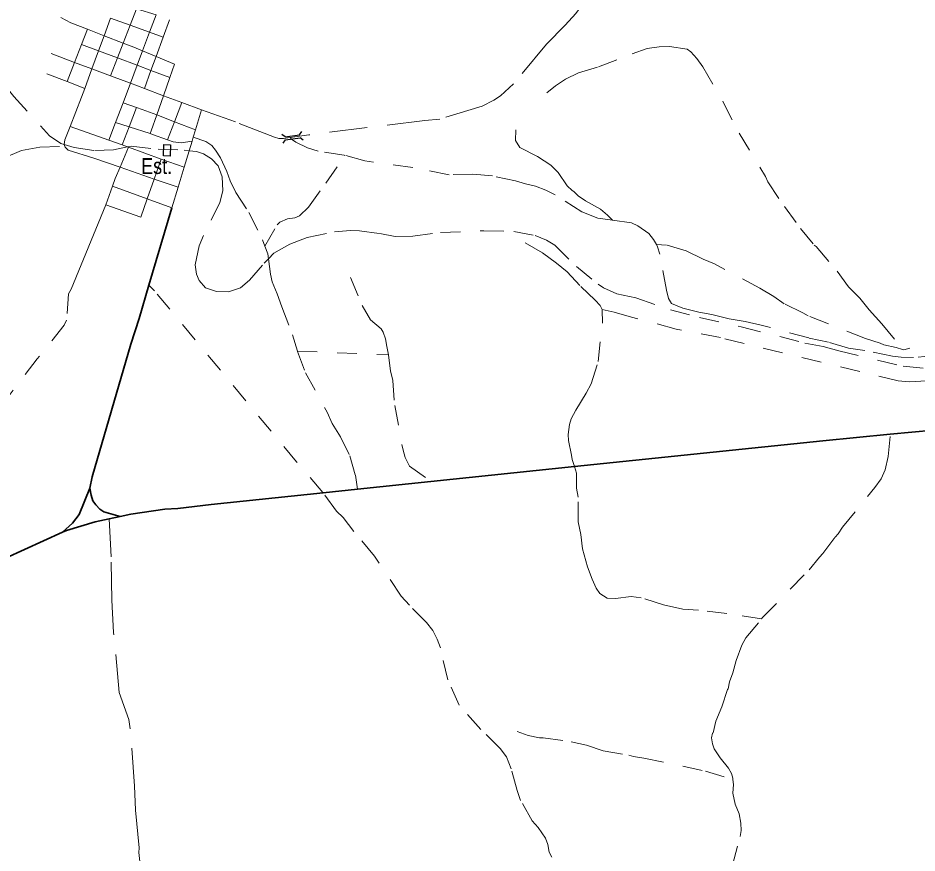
# Model space of a CAD drawing. Extents: x 783.4 to 809.8, y 7536.4 to 7564.6.
# Drawn here: x 790.875 to 795.406, y 7553.23 to 7557.441 of the extents above; entities that cross this region are included whole.
import ezdxf
from ezdxf.enums import TextEntityAlignment as Align

# ---------------------------------------------------------------- set-up
doc = ezdxf.new("R2010")
doc.units = 0
doc.header["$LTSCALE"] = 0.032
for name, pattern in [('DOTTED', [1.5, 0.3, -1.2]), ('LONG_DASHED', [7.5, 6, -1.5]), ('MEDIUM_DASHED', [4.5, 3, -1.5])]:
    doc.linetypes.add(name, pattern=pattern)
for name, color, linetype, lineweight in [('10', 7, 'Continuous', 25), ('18', 7, 'DOTTED', 13), ('2', 7, 'Continuous', 35), ('28', 7, 'Continuous', 25), ('5', 7, 'LONG_DASHED', 13), ('6', 7, 'MEDIUM_DASHED', 13), ('7', 7, 'DOTTED', 13), ('8', 7, 'Continuous', 13)]:
    doc.layers.add(name, color=color, linetype=linetype, lineweight=lineweight)
doc.layers.add('61', color=7, linetype='Continuous')

msp = doc.modelspace()

# ---------------------------------------------------------------- linework, layer by layer
at = {"layer": '10'}
for p, q in [((792.2208, 7556.8422), (792.205, 7556.8543)), ((792.2111, 7556.8105), (792.223, 7556.8264)), ((792.223, 7556.8264), (792.2963, 7556.8367)), ((792.3123, 7556.8247), (792.2963, 7556.8367))]:
    msp.add_line(p, q, dxfattribs=at)
msp.add_lwpolyline([(792.2208, 7556.8422), (792.2941, 7556.8525), (792.3061, 7556.8685)], dxfattribs=at)
at = {"layer": '18'}
for points in [[(790.5277, 7557.551), (790.6798, 7557.3347), (790.764, 7557.1684), (790.8086, 7557.1021), (790.8537, 7557.0458), (791.0331, 7556.8465), (791.0907, 7556.8075), (791.1076, 7556.8025)], [(791.1076, 7556.8025), (791.1579, 7556.7878), (791.2621, 7556.7727), (791.3563, 7556.7765), (791.4272, 7556.7908)], [(791.4272, 7556.7908), (791.4445, 7556.7943), (791.5807, 7556.7789), (791.712, 7556.7751), (791.7377, 7556.7721)], [(791.7377, 7556.7721), (791.7752, 7556.7676), (791.8102, 7556.7563), (791.8493, 7556.7309), (791.8834, 7556.6962), (791.9034, 7556.6407), (791.9065, 7556.5693), (791.8924, 7556.511), (791.8098, 7556.3451), (791.7887, 7556.2925), (791.7677, 7556.1957), (791.7747, 7556.1497), (791.7872, 7556.1182), (791.8203, 7556.0806), (791.8744, 7556.0618), (791.9365, 7556.06), (791.9957, 7556.0797), (792.0418, 7556.1192), (792.1149, 7556.2056), (792.1371, 7556.2273)], [(792.1371, 7556.2273), (792.165, 7556.2545), (792.2457, 7556.301), (792.3319, 7556.3349), (792.4702, 7556.3631), (792.5514, 7556.3696), (792.5965, 7556.3687), (792.6982, 7556.3541), (792.7754, 7556.3391), (792.8656, 7556.341), (793.0049, 7556.3588), (793.2229, 7556.3687), (793.3732, 7556.364), (793.4819, 7556.3447), (793.5391, 7556.3212), (793.5801, 7556.2958), (793.6905, 7556.1877), (793.7982, 7556.0989), (793.8263, 7556.0801), (793.8934, 7556.05), (793.9896, 7556.0294), (794.1635, 7555.9697), (794.3098, 7555.9302), (794.5203, 7555.8842), (794.8405, 7555.802), (794.9337, 7555.7851), (795.0124, 7555.7621), (795.3371, 7555.685), (795.4657, 7555.6734)]]:
    msp.add_lwpolyline(points, dxfattribs=at)
at = {"layer": '2'}
for p, q in [((791.6509, 7556.4844), (791.5349, 7556.0935)), ((792.9563, 7555.1033), (793.6797, 7555.1787)), ((791.3337, 7554.9157), (791.389, 7554.9276))]:
    msp.add_line(p, q, dxfattribs=at)
for points in [[(791.5349, 7556.0935), (791.4854, 7555.9265), (791.4441, 7555.7966), (791.2483, 7555.1272), (791.2375, 7555.0707), (791.2373, 7555.0702)], [(793.6797, 7555.1787), (794.9319, 7555.3091), (795.2716, 7555.3423), (795.4886, 7555.3627)], [(792.4125, 7555.0467), (792.5856, 7555.0647), (792.9563, 7555.1033)], [(791.2373, 7555.0702), (791.1834, 7554.9382), (791.1498, 7554.8937), (791.0992, 7554.8479)], [(791.2373, 7555.0702), (791.2433, 7555.0356), (791.2525, 7555.0067), (791.2672, 7554.9857), (791.288, 7554.9647), (791.3074, 7554.9509), (791.389, 7554.9276)], [(791.389, 7554.9276), (791.4441, 7554.9395), (791.6155, 7554.9639), (791.6796, 7554.9677), (791.8485, 7554.9879), (792.4125, 7555.0467)], [(791.0992, 7554.8479), (791.1199, 7554.8573), (791.2632, 7554.9005), (791.3337, 7554.9157)], [(788.9236, 7554.2237), (789.0729, 7554.2243), (789.2498, 7554.221), (789.4603, 7554.2361), (789.6116, 7554.2549), (789.8015, 7554.2901), (789.9318, 7554.324), (790.021, 7554.3531), (790.274, 7554.4729), (790.3763, 7554.5133), (790.5902, 7554.6163), (790.6187, 7554.6293), (791.0992, 7554.8479)]]:
    msp.add_lwpolyline(points, dxfattribs=at)
at = {"layer": '28'}
msp.add_lwpolyline([(791.6083, 7556.7454), (791.6103, 7556.8024), (791.6442, 7556.8012), (791.6422, 7556.7442)], close=True, dxfattribs=at)
at = {"layer": '5'}
for points in [[(793.7415, 7559.6693), (793.6938, 7559.5981), (793.6538, 7559.5517), (793.6122, 7559.5165), (793.5506, 7559.4757), (793.3394, 7559.3621), (793.2354, 7559.2901), (793.1594, 7559.2301), (792.8826, 7558.9893), (792.6978, 7558.8372), (792.5706, 7558.7236), (792.3033, 7558.5012), (792.2673, 7558.4596), (792.0593, 7558.1564), (791.7425, 7557.7044), (791.6062, 7557.3449)], [(793.9831, 7557.8046), (793.8466, 7557.6892), (793.7962, 7557.6276), (793.7498, 7557.5508), (793.6866, 7557.4644), (793.633, 7557.4044), (793.5386, 7557.3084), (793.3722, 7557.1084), (793.3066, 7557.0484), (793.2738, 7557.026), (793.2148, 7556.9963), (793.0003, 7556.9315), (792.9252, 7556.9249), (792.34, 7556.8516), (792.2471, 7556.8378)], [(791.0906, 7557.4429), (791.1407, 7557.4175), (791.2243, 7557.3844)], [(792.2471, 7556.8378), (792.2137, 7556.8328), (792.1897, 7556.8337), (792.1676, 7556.8394), (791.9707, 7556.9169), (791.7997, 7556.9776)], [(791.8674, 7552.2937), (791.8681, 7552.301), (791.8665, 7552.349), (791.8593, 7552.397), (791.8465, 7552.445), (791.8249, 7552.493), (791.7761, 7552.565), (791.6377, 7552.7362), (791.5801, 7552.8154), (791.5377, 7552.8962), (791.5241, 7552.9442), (791.5001, 7553.0882), (791.4841, 7553.2322), (791.4849, 7553.2562), (791.4665, 7553.4482), (791.4617, 7553.5683), (791.4409, 7553.8563), (791.4329, 7553.9043), (791.3848, 7554.0396), (791.3569, 7554.3427), (791.3481, 7554.5059), (791.3441, 7554.7235), (791.3337, 7554.9157)]]:
    msp.add_lwpolyline(points, dxfattribs=at)
at = {"layer": '6'}
for points in [[(791.7581, 7556.8397), (791.8213, 7556.8178), (791.8511, 7556.7985), (791.871, 7556.7752), (791.8952, 7556.7365), (791.9271, 7556.6666), (791.9435, 7556.6206), (791.9719, 7556.5613), (792.039, 7556.4604), (792.1072, 7556.3232), (792.1192, 7556.2913)], [(790.8012, 7556.7351), (790.8928, 7556.7731), (790.9844, 7556.7903), (791.1109, 7556.793)], [(792.1192, 7556.2913), (792.1338, 7556.2523), (792.1371, 7556.2273)], [(792.1371, 7556.2273), (792.1473, 7556.1497), (792.1559, 7556.1104), (792.1818, 7556.0507), (792.2038, 7555.9848), (792.2585, 7555.8436), (792.2829, 7555.7615)], [(792.4125, 7555.0467), (792.4116, 7555.0478), (792.2792, 7555.2032), (791.562, 7556.0658), (791.5349, 7556.0935)], [(791.1424, 7556.073), (791.1296, 7556.051), (791.12, 7555.9173), (791.108, 7555.892), (790.9719, 7555.7223), (790.7713, 7555.4611)], [(792.2829, 7555.7615), (792.2837, 7555.7587), (792.3242, 7555.6521), (792.4326, 7555.454), (792.4585, 7555.3971), (792.5002, 7555.3299), (792.5474, 7555.2339), (792.5751, 7555.1357), (792.5856, 7555.0647)], [(793.5653, 7553.2099), (793.552, 7553.2341), (793.5446, 7553.2737), (793.5335, 7553.3056), (793.4958, 7553.3583), (793.4658, 7553.3926), (793.4081, 7553.4953), (793.3904, 7553.546), (793.3611, 7553.6552), (793.3374, 7553.7162), (793.3056, 7553.7579), (793.2072, 7553.8536), (793.0988, 7553.9761), (793.0411, 7554.1044), (793.0037, 7554.2657), (792.9875, 7554.3087), (792.9653, 7554.3524), (792.9339, 7554.3923), (792.8473, 7554.4797), (792.8066, 7554.5262), (792.6716, 7554.7277), (792.5673, 7554.8519), (792.5144, 7554.9216), (792.4804, 7554.9542), (792.4125, 7555.0467)]]:
    msp.add_lwpolyline(points, dxfattribs=at)
at = {"layer": '7'}
msp.add_line((792.2829, 7555.7615), (792.7415, 7555.7425), dxfattribs=at)
for points in [[(793.5401, 7557.0641), (793.5833, 7557.0995), (793.634, 7557.1329), (793.6999, 7557.1643), (793.8002, 7557.1946), (793.9706, 7557.2612), (794.0466, 7557.2868), (794.1066, 7557.2964), (794.1594, 7557.298), (794.2474, 7557.2844), (794.2658, 7557.2708), (794.297, 7557.2372), (794.3266, 7557.1948), (794.4298, 7557.0164), (794.509, 7556.8604), (794.6426, 7556.6412), (794.6546, 7556.6148), (794.7378, 7556.49), (794.8194, 7556.3804), (794.8874, 7556.2964), (794.8978, 7556.2892), (795.0035, 7556.164), (795.0605, 7556.0856), (795.1174, 7556.028), (795.1644, 7555.9701), (795.2295, 7555.8994), (795.3334, 7555.7694)], [(793.3841, 7556.8765), (793.3818, 7556.8236), (793.405, 7556.7876), (793.4938, 7556.7428), (793.5602, 7556.6988), (793.597, 7556.6628), (793.6434, 7556.5956), (793.6674, 7556.5716), (793.677, 7556.566), (793.6978, 7556.5452), (793.7346, 7556.5196), (793.8106, 7556.4764), (793.8466, 7556.4476), (793.8719, 7556.4216)], [(792.5228, 7556.748), (792.5183, 7556.7492), (792.3885, 7556.7697), (792.3345, 7556.7863), (792.2746, 7556.8148), (792.2538, 7556.8293), (792.2471, 7556.8378)], [(792.1192, 7556.2913), (792.1808, 7556.398), (792.195, 7556.4123), (792.2332, 7556.4287), (792.2703, 7556.4328), (792.2933, 7556.444), (792.3391, 7556.488), (792.4264, 7556.6078), (792.5228, 7556.748)], [(793.8719, 7556.4216), (793.797, 7556.432), (793.7175, 7556.4629), (793.5828, 7556.5489), (793.5355, 7556.5725), (793.4829, 7556.5933), (793.4322, 7556.6047), (793.3827, 7556.62), (793.2658, 7556.645), (793.1674, 7556.6533), (793.0476, 7556.6511), (792.8649, 7556.6864), (792.6233, 7556.7208), (792.5228, 7556.748)], [(794.0924, 7556.2992), (794.0781, 7556.3245), (794.0544, 7556.3536), (793.999, 7556.3939), (793.9671, 7556.4084), (793.8719, 7556.4216)], [(793.8195, 7555.972), (793.8086, 7555.9908), (793.7845, 7556.0183), (793.7065, 7556.0923), (793.6427, 7556.1603), (793.5891, 7556.2051), (793.5181, 7556.2567), (793.4246, 7556.3105)], [(795.5113, 7555.7409), (795.3882, 7555.7289), (795.3264, 7555.7306), (795.2828, 7555.7355), (795.1429, 7555.7646), (795.0602, 7555.7755), (794.9594, 7555.8059), (794.8601, 7555.8278), (794.6203, 7555.893), (794.5393, 7555.9107), (794.4586, 7555.9239), (794.3721, 7555.9454), (794.307, 7555.9572), (794.226, 7555.9784), (794.169, 7556.0006), (794.1539, 7556.0272), (794.1436, 7556.0688), (794.1103, 7556.2506), (794.0988, 7556.2877), (794.0924, 7556.2992)], [(795.3334, 7555.7694), (795.3011, 7555.7795), (795.2395, 7555.7923), (795.2211, 7555.8011), (795.1458, 7555.8251), (794.8578, 7555.9387), (794.8314, 7555.9547), (794.7372, 7555.9997), (794.685, 7556.0367), (794.6137, 7556.0785), (794.3858, 7556.2014), (794.3285, 7556.2253), (794.2432, 7556.2671), (794.1439, 7556.2957), (794.0924, 7556.2992)], [(792.5512, 7556.1323), (792.6087, 7555.9921), (792.6512, 7555.9183), (792.7045, 7555.8741), (792.7153, 7555.8575), (792.7264, 7555.8229), (792.7339, 7555.7841), (792.7415, 7555.7425)], [(793.6797, 7555.1787), (793.6682, 7555.2145), (793.665, 7555.2371), (793.649, 7555.3107), (793.6474, 7555.3403), (793.6546, 7555.3907), (793.6634, 7555.4203), (793.6858, 7555.4643), (793.7386, 7555.5491), (793.7642, 7555.5971), (793.7986, 7555.7091), (793.8202, 7555.9027), (793.8195, 7555.972)], [(795.5115, 7555.6254), (795.4536, 7555.6118), (795.3681, 7555.6064), (795.3116, 7555.6118), (794.4159, 7555.8292), (794.1927, 7555.8727), (793.9673, 7555.9333), (793.88, 7555.958), (793.8195, 7555.972)], [(795.5643, 7555.8251), (795.3395, 7555.7675), (795.3334, 7555.7694)], [(792.7415, 7555.7425), (792.7443, 7555.727), (792.753, 7555.6627), (792.7634, 7555.6139), (792.7738, 7555.4867), (792.8154, 7555.2611), (792.8258, 7555.2243), (792.8474, 7555.1819), (792.9563, 7555.1033)], [(794.6229, 7554.4115), (794.628, 7554.4177), (794.8626, 7554.6587), (794.9138, 7554.7227), (794.9322, 7554.7411), (794.993, 7554.8235), (795.0082, 7554.8395), (795.0306, 7554.8739), (795.1939, 7555.0731), (795.2251, 7555.1179), (795.2451, 7555.1627), (795.2603, 7555.2307), (795.2716, 7555.3423)], [(794.6229, 7554.4115), (794.4482, 7554.4387), (794.305, 7554.4547), (794.2266, 7554.4603), (794.129, 7554.4811), (794.0162, 7554.5171), (793.9655, 7554.5237), (793.8858, 7554.5139), (793.8442, 7554.5163), (793.8066, 7554.5395), (793.7882, 7554.5667), (793.7682, 7554.6107), (793.745, 7554.6739), (793.7194, 7554.7651), (793.7114, 7554.8371), (793.6986, 7554.9011), (793.6986, 7555.0251), (793.6906, 7555.0707), (793.6898, 7555.1459), (793.6797, 7555.1787)], [(794.4785, 7553.6013), (794.4778, 7553.6071), (794.4711, 7553.6321), (794.4556, 7553.6578), (794.4146, 7553.7099), (794.3834, 7553.7555), (794.3746, 7553.7803), (794.3706, 7553.8115), (794.3754, 7553.8347), (794.3786, 7553.8363), (794.3922, 7553.8947), (794.4218, 7553.9683), (794.4506, 7554.0555), (794.4538, 7554.0579), (794.4618, 7554.0939), (794.4778, 7554.1395), (794.4946, 7554.2019), (794.5234, 7554.2787), (794.5426, 7554.3147), (794.6229, 7554.4115)], [(793.3911, 7553.8428), (793.4469, 7553.8227), (793.5026, 7553.8106), (793.5218, 7553.8115), (793.6634, 7553.7907), (793.7402, 7553.7739), (793.8234, 7553.7459), (793.9538, 7553.7235), (793.977, 7553.7163), (794.0299, 7553.709), (794.3393, 7553.6438), (794.4785, 7553.6013)], [(794.4777, 7553.1222), (794.4766, 7553.1691), (794.5146, 7553.313), (794.5194, 7553.3442), (794.5186, 7553.381), (794.509, 7553.4274), (794.489, 7553.4762), (794.4778, 7553.5315), (794.4815, 7553.5759), (794.4785, 7553.6013)]]:
    msp.add_lwpolyline(points, dxfattribs=at)
at = {"layer": '8'}
for p, q in [((791.4396, 7557.4046), (791.4717, 7557.4872)), ((791.4045, 7557.3143), (791.4396, 7557.4046)), ((791.2243, 7557.3844), (791.3091, 7557.3514)), ((791.3091, 7557.3514), (791.2808, 7557.2749)), ((791.3091, 7557.3514), (791.4045, 7557.3143)), ((791.5382, 7557.3693), (791.5025, 7557.2748)), ((791.6062, 7557.3449), (791.5382, 7557.3693)), ((791.1943, 7557.307), (791.2808, 7557.2749)), ((791.3755, 7557.2397), (791.4045, 7557.3143)), ((791.6062, 7557.3449), (791.5704, 7557.2465)), ((791.0413, 7557.2615), (791.1594, 7557.2173)), ((791.2808, 7557.2749), (791.2473, 7557.1844)), ((791.2808, 7557.2749), (791.3755, 7557.2397)), ((791.5025, 7557.2748), (791.4753, 7557.2026)), ((791.5025, 7557.2748), (791.5704, 7557.2465)), ((791.1594, 7557.2173), (791.1217, 7557.1201)), ((791.1594, 7557.2173), (791.2473, 7557.1844)), ((791.3404, 7557.1495), (791.3755, 7557.2397)), ((791.3755, 7557.2397), (791.4753, 7557.2026)), ((791.5704, 7557.2465), (791.545, 7557.1767)), ((791.2473, 7557.1844), (791.211, 7557.0861)), ((791.2473, 7557.1844), (791.3404, 7557.1495)), ((791.4753, 7557.2026), (791.441, 7557.1119)), ((791.4753, 7557.2026), (791.545, 7557.1767)), ((791.545, 7557.1767), (791.5118, 7557.0854)), ((791.545, 7557.1767), (791.6398, 7557.1415)), ((791.3404, 7557.1495), (791.441, 7557.1119)), ((791.6079, 7557.0494), (791.5742, 7556.9521)), ((791.404, 7557.0138), (791.4719, 7556.9901)), ((791.4719, 7556.9901), (791.4346, 7556.8928)), ((791.7006, 7557.0147), (791.6637, 7556.9181)), ((791.5742, 7556.9521), (791.6637, 7556.9181)), ((791.7997, 7556.9776), (791.7696, 7556.8778)), ((791.3666, 7556.9148), (791.3326, 7556.8247)), ((791.3666, 7556.9148), (791.4346, 7556.8928)), ((791.6637, 7556.9181), (791.6289, 7556.8268)), ((791.6637, 7556.9181), (791.7696, 7556.8778)), ((791.1373, 7556.8947), (791.3326, 7556.8247)), ((791.4346, 7556.8928), (791.3994, 7556.8008)), ((791.4346, 7556.8928), (791.5417, 7556.8581)), ((791.7524, 7556.8207), (791.7377, 7556.7721)), ((791.389, 7556.689), (791.4315, 7556.7893)), ((791.4272, 7556.7908), (791.4315, 7556.7893)), ((791.4315, 7556.7893), (791.5969, 7556.73)), ((791.7377, 7556.7721), (791.7125, 7556.6886)), ((791.5614, 7556.6292), (791.5969, 7556.73)), ((791.5969, 7556.73), (791.7125, 7556.6886)), ((791.389, 7556.689), (791.5614, 7556.6292)), ((791.5263, 7556.5296), (791.5614, 7556.6292)), ((791.5614, 7556.6292), (791.6819, 7556.5873)), ((791.3167, 7556.4995), (791.3508, 7556.5933)), ((791.3508, 7556.5933), (791.5263, 7556.5296)), ((791.1424, 7556.073), (791.3167, 7556.4995)), ((791.5263, 7556.5296), (791.6509, 7556.4844))]:
    msp.add_line(p, q, dxfattribs=at)
for points in [[(791.4717, 7557.4872), (791.5712, 7557.4568), (791.5382, 7557.3693), (791.4396, 7557.4046)], [(791.4396, 7557.4046), (791.3417, 7557.4396), (791.3091, 7557.3514)], [(791.2243, 7557.3844), (791.1943, 7557.307), (791.1594, 7557.2173)], [(791.4045, 7557.3143), (791.4585, 7557.2932), (791.5025, 7557.2748)], [(791.5704, 7557.2465), (791.6628, 7557.208), (791.6398, 7557.1415)], [(791.0196, 7557.1589), (791.1217, 7557.1201), (791.211, 7557.0861)], [(791.6398, 7557.1415), (791.6079, 7557.0494), (791.7006, 7557.0147), (791.7997, 7556.9776)], [(791.211, 7557.0861), (791.1948, 7557.0424), (791.1373, 7556.8947)], [(791.441, 7557.1119), (791.404, 7557.0138), (791.3666, 7556.9148)], [(791.441, 7557.1119), (791.5118, 7557.0854), (791.6079, 7557.0494)], [(791.4719, 7556.9901), (791.5008, 7556.98), (791.5742, 7556.9521)], [(791.5742, 7556.9521), (791.5465, 7556.8722), (791.5417, 7556.8581)], [(791.1373, 7556.8947), (791.1111, 7556.8274), (791.1076, 7556.8025)], [(791.5417, 7556.8581), (791.5533, 7556.8543), (791.6289, 7556.8268)], [(791.7696, 7556.8778), (791.7581, 7556.8397), (791.7524, 7556.8207)], [(791.3326, 7556.8247), (791.3994, 7556.8008), (791.4272, 7556.7908)], [(791.6289, 7556.8268), (791.6573, 7556.8165), (791.6975, 7556.8123), (791.7524, 7556.8207)], [(791.1076, 7556.8025), (791.1076, 7556.8025), (791.1109, 7556.793)], [(791.1109, 7556.793), (791.1121, 7556.7896), (791.1273, 7556.7743), (791.2563, 7556.7351), (791.389, 7556.689)], [(791.3508, 7556.5933), (791.3648, 7556.6318), (791.389, 7556.689)], [(791.7125, 7556.6886), (791.6819, 7556.5873), (791.6509, 7556.4844)], [(791.3167, 7556.4995), (791.4939, 7556.4376), (791.5263, 7556.5296)]]:
    msp.add_lwpolyline(points, dxfattribs=at)

# ---------------------------------------------------------------- texts
at = {"layer": '61', "width": 0.85}
msp.add_text('Est.', height=0.08, dxfattribs=at).set_placement((791.6518, 7556.6546), align=Align.RIGHT)

doc.saveas('drawing.dxf')
